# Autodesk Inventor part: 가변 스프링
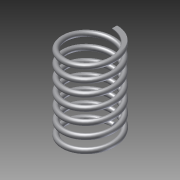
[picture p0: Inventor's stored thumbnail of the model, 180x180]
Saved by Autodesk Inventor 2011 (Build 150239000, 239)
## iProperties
Created: 2014-12
Part Number: 가변 스프링
Document SubType Name: Modeling
Designer: user
Density: 1 g/cm^3
Author: user
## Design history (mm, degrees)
sketch "스케치2"
  geometry: L1 (0, 0)-(24, 0); L2 (24, 0)-(24, 84.25); L3 (24, 84.25)-(0, 84.25); L4 (0, 84.25)-(0, 0); C1 r 2.5 at (24, 0)
  constraints: 8 end point, 2 parallel, 1 centre point, 1 coincident, 1 horizontal, 1 perpendicular
  dimensions: "d0" = 48 diameter of L2 L4; "d2" = 5 diameter of C1; "d4" = 84.25 distance between parallel lines of L1 L3 (derived)
feature "코일1" sketch "스케치2" pitch "d5" = 10; turns "d7" = 7; dims "d6" = 84.25, "d8" = 0, angle "d9" = 90 deg, angle "d10" = 90 deg, "d11" = 0, "d12" = 0
node "작업 평면1"
feature "분할1"
feature "분할2"
node "솔리드1"
other parameters: "d13" = 84.25
